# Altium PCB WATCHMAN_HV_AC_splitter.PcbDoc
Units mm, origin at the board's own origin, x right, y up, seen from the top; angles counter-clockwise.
Board outline 37 x 44 mm, 2 copper layers (Top Layer - SIG1, Bottom Layer - SIG4), stack 1.62 mm thick; 16 components, 8 nets, 33 pads, 16 vias.
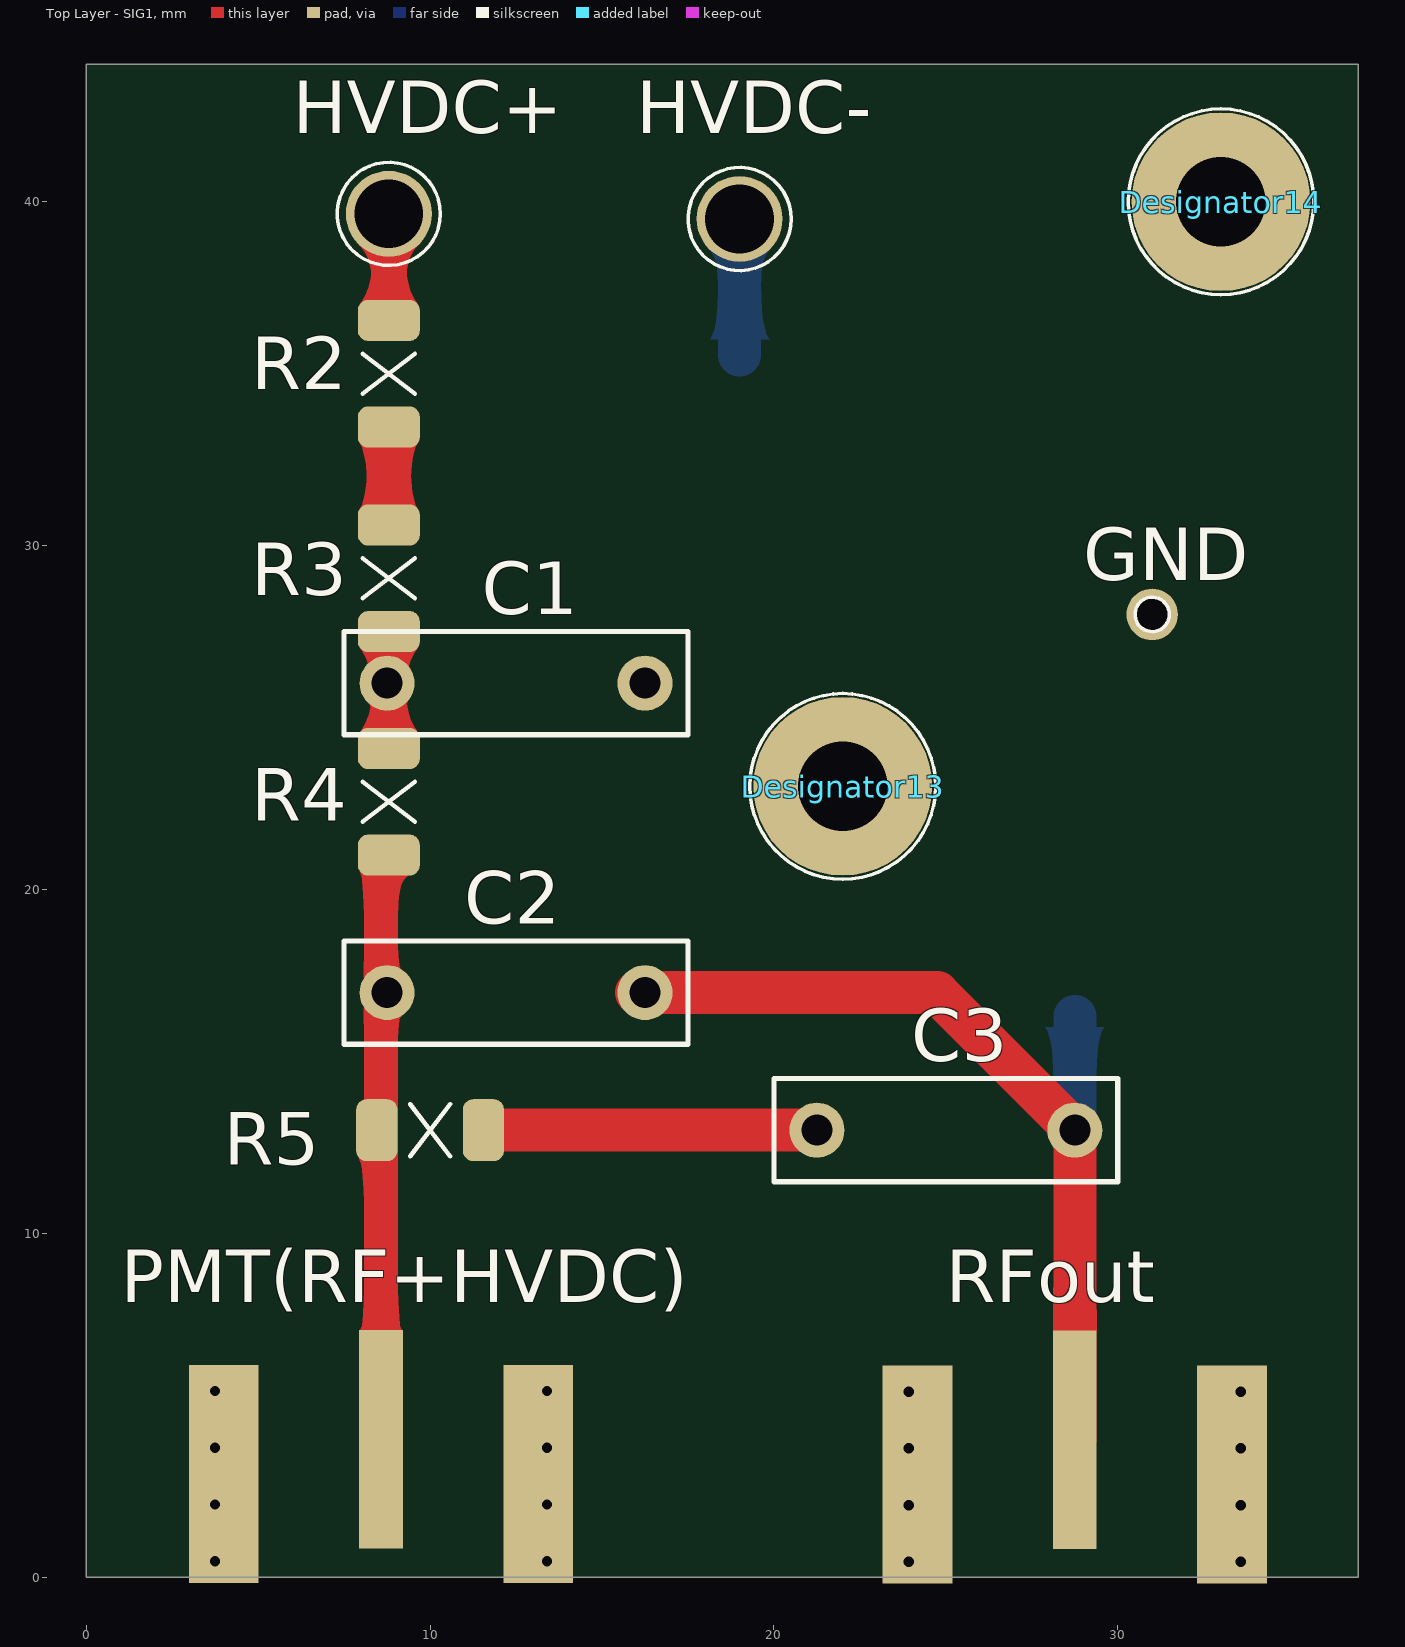
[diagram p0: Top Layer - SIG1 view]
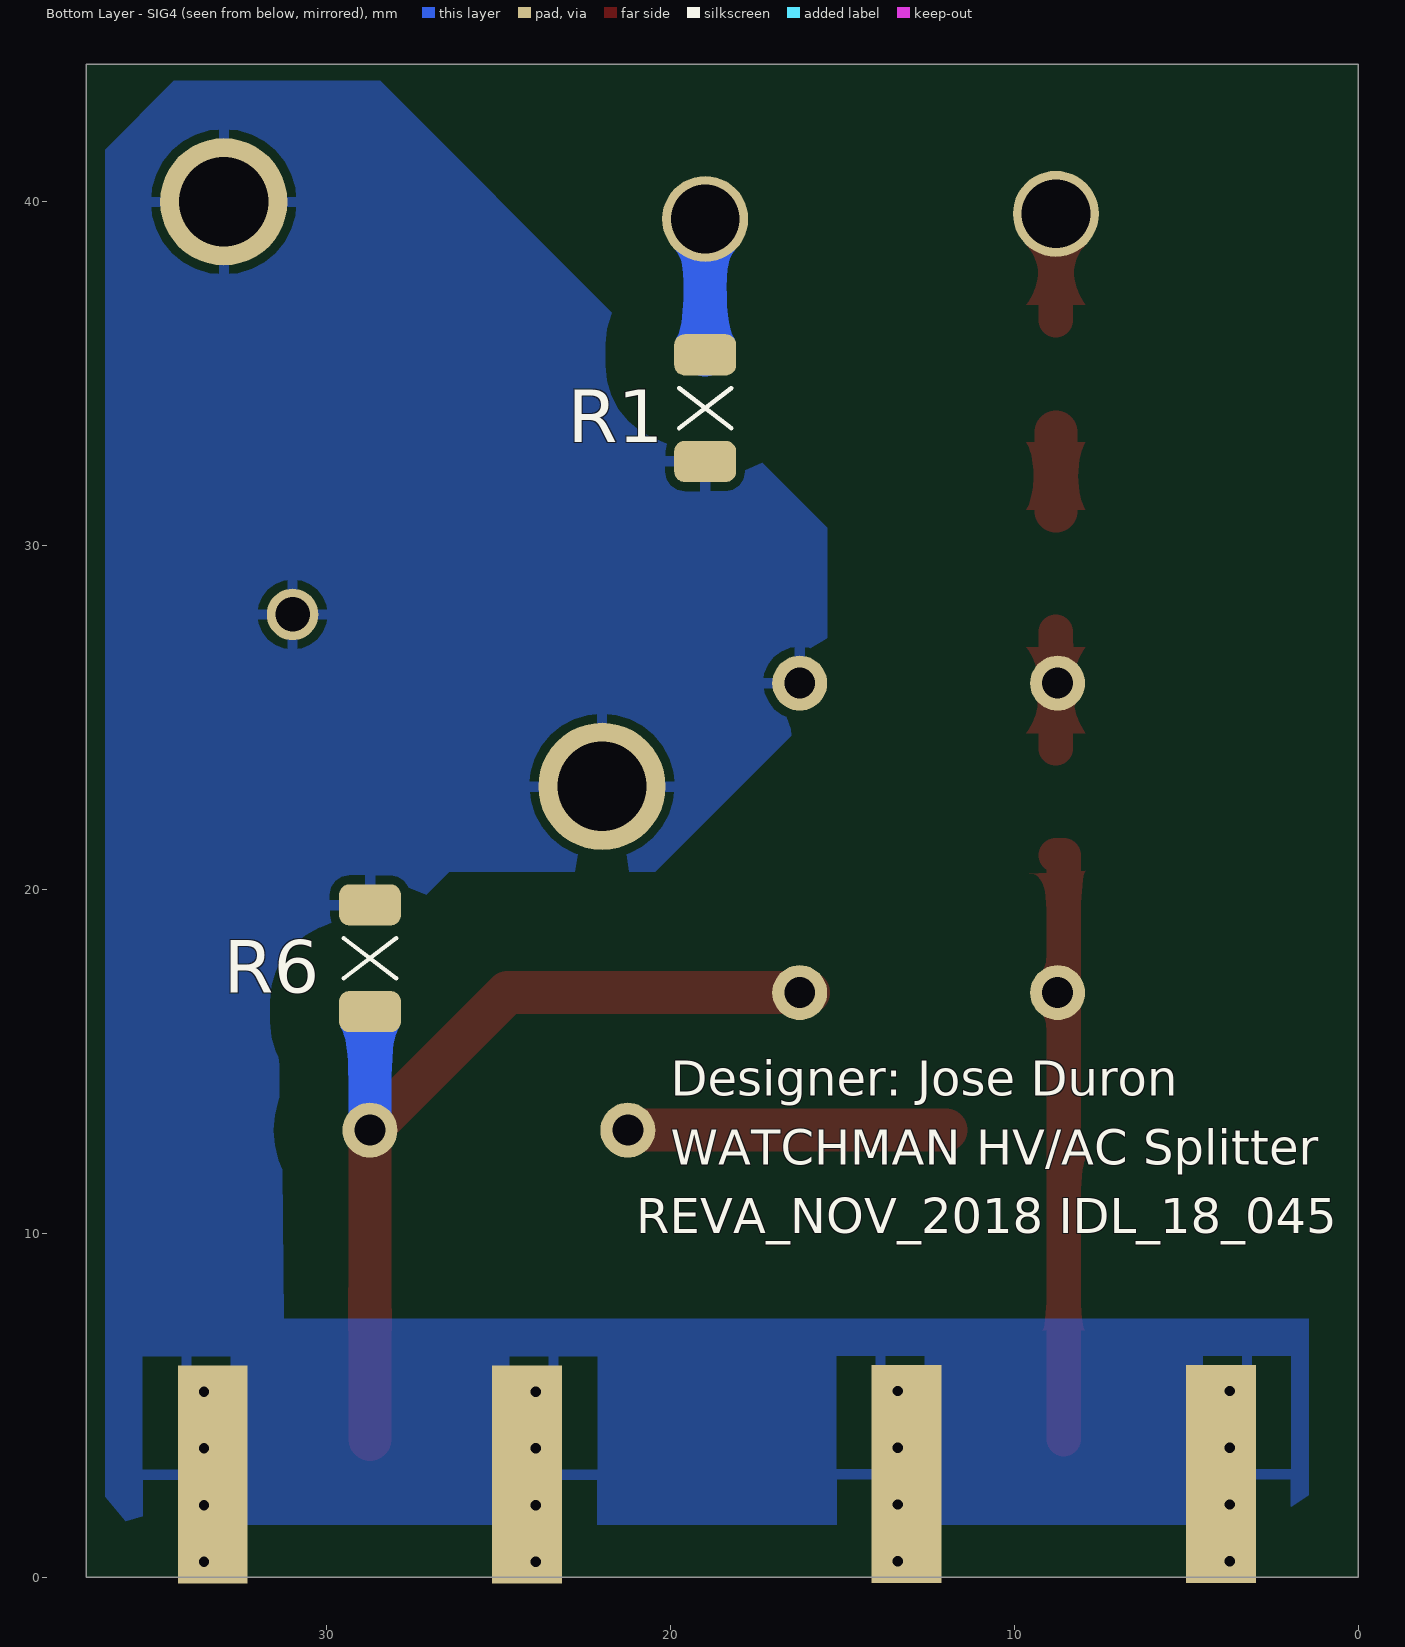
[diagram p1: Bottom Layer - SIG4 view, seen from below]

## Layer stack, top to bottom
Top Solder: solder mask 0.0102, Solder Resist, Dk 3.5
Top Layer - SIG1: signal copper 0.035
Dielectric 1: core 1.55, FR-4, Dk 4.2
Bottom Layer - SIG4: signal copper 0.035
Bottom Solder: solder mask 0.0102, Solder Resist, Dk 3.5

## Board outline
0,0 37,0 37,44 0,44

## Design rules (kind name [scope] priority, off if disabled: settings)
Clearance Clearance_Diff [InAnyDifferentialPair  or InNetClass('INPUT') vs InNamedPolygon('L4_5VAN') or InNamedPolygon('L3_5VAP') or InNamedPolygon('L1_GND') OR InNamedPolygon('L6_GND')   or InNamedPolygon('L3_GND') or InNamedPolygon('L4_GND')] p1: gap=0.381 ignorepadtopadclearanceinfootprint=FALSE except(0: Arc-Hole Track-Hole SMDPad-Hole THPad-Hole Via-Hole Fill-Hole Poly-Hole Region-Hole Text-Hole)
Clearance Clearance_RF [InNetClass('RF') or InNet('HV_BIAS') or InNet('NetCN1_235') vs InNamedPolygon('L4_5VAN') or InNamedPolygon('L3_5VAP') or InNamedPolygon('L1_GND') OR InNamedPolygon('L6_GND')   or InNamedPolygon('L3_GND') or InNamedPolygon('L4_GND')] p2: gap=0.508 ignorepadtopadclearanceinfootprint=FALSE except(0: Arc-Hole Track-Hole SMDPad-Hole THPad-Hole Via-Hole Fill-Hole Poly-Hole Region-Hole Text-Hole)
Clearance Clearance_Poly [InNamedPolygon('L4_5VAN') or InNamedPolygon('L3_5VAP')  or InNamedPolygon('L1_GND')     OR InNamedPolygon('L6_GND')  or InNamedPolygon('L3_GND') or InNamedPolygon('L4_GND')] p3: gap=0.203 ignorepadtopadclearanceinfootprint=FALSE except(0: Arc-Hole Track-Hole SMDPad-Hole THPad-Hole Via-Hole Fill-Hole Poly-Hole Region-Hole Text-Hole; 1: Arc-THPad Track-THPad SMDPad-THPad THPad-THPad)
Clearance Clearance_KeepOut [Iskeepout] p4 off: gap=0.508 ignorepadtopadclearanceinfootprint=FALSE except(0: Arc-Hole Track-Hole SMDPad-Hole THPad-Hole Via-Hole Fill-Hole Poly-Hole Region-Hole Text-Hole)
Clearance [All] p5: gap=2 ignorepadtopadclearanceinfootprint=TRUE except(0: Arc-Text Arc-Hole Track-Text Track-Hole SMDPad-Text SMDPad-Hole THPad-Text THPad-Hole Via-Text Via-Hole Fill-Text Fill-Hole Poly-Text Poly-Hole Region-Text Region-Hole Text-Text Text-Hole; 0.152: Arc-Arc Arc-Track Arc-SMDPad Arc-Via Track-Track Track-SMDPad Track-Via SMDPad-SMDPad SMDPad-Via THPad-Via Via-Via)
ComponentClearance [All] p1 off: gap=0.254 collisioncheckmode=3 verticalgap=0.254 showdistances=FALSE
DiffPairsRouting [All] p1: maxlimit=0.254 minlimit=0.102 mostfreqgap=0.152 toplayer_minwidth=0.102 toplayer_maxwidth=0.305 toplayer_prefwidth=0.203 bottomlayer_minwidth=0.102 bottomlayer_maxwidth=0.305 bottomlayer_prefwidth=0.203 maxuncoupledlength=12.7
Height [All] p1 off: minheight=0 maxheight=25.4 prefheight=12.7
HoleSize [All] p1: absolutevalues=TRUE maxlimit=3.3 minlimit=0.3 maxpercent=80.000 minpercent=20.000
MinimumSolderMaskSliver [All] p1: minsoldermaskwidth=0.127
NetAntennae [All] p1 off: netantennaetolerance=0
PlaneClearance [All] p1: clearance=0.254
PlaneConnect PlaneConnect_vIA [ISvIA] p1: planeconnectstyle=Direct reliefexpansion=0.508 reliefentries=4 reliefconductorwidth=0.254 reliefairgap=0.254
PlaneConnect [All] p2: planeconnectstyle=Direct reliefexpansion=0.305 reliefentries=4 reliefconductorwidth=0.381 reliefairgap=0.203
PolygonConnect PolygonConnect_Via [IsVia or HasFootprint('ChipFET1206-8') or HasFootprint('MAXB2MPCBV') or HasFootprint('MAXB5MPCBV') or HasFootprint('MAXB6MPCBV') or HasFootprint('PINHDR2X20H') or Hasfootprint('PINHDR2X13H')  or HasFootprint('CC1210-X2Y') or HasFootprint('L-COMMCHOKE-4') or HasFootprint('CTC-D7343-43')] p1: connectstyle=Direct reliefconductorwidth=0.254 reliefentries=4 polygonreliefangle="90 Angle" airgapwidth=0.254
PolygonConnect PolygonConnect_Main [All] p2: connectstyle=Relief reliefconductorwidth=0.305 reliefentries=4 polygonreliefangle="90 Angle" airgapwidth=0.254
RoutingVias [All] p1: holewidth=0.3 width=0.65 viastyle="Through Hole" minholewidth=0.3 minwidth=0.65 maxholewidth=1 maxwidth=1.5
SilkToSilkClearance [All] p1: silktosilkclearance=0.127
SilkToSolderMaskClearance SilkscreenOverComponentPads [IsPad] p1: minsilkscreentomaskgap=0.127 clearancetoexposedcopper=TRUE
SolderMaskExpansion [All] p1: expansion=0.051
Width Width_Logo [HasFootprint('ITECH_LOGO')] p1: maxlimit=0.254 minlimit=0.025 preferedwidth=0.051
Width [All] p2: maxlimit=3.81 minlimit=0.1 preferedwidth=1 bottomlayer_minwidth=0 minimp=50.000000 maximp=50.000000 favimp=50.000000
20 further rules are at their usual default settings.

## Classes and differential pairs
component class HV_AC_splitter: C1 C2 C3 GND HVDC+ HVDC- PMT(RF+HVDC) R1 R2 R3 R4 R5 R6 RFout

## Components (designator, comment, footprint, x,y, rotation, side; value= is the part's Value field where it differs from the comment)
C1 "47nF" CAPNQR7.5-3X10X8.5 12.5,26 r0 top
C2 "1nF" CAPNQR7.5-3X10X8.5 12.5,17 r0 top
C3 "4.7nF" CAPNQR7.5-3X10X8.5 25,13 r0 top
Designator13 "Comment" MH2.5SCRPL 22,23 r0 top
Designator14 "Comment" MH2.5SCRPL 33,40 r0 top
GND "TEST-POINT-SURFACE-MOUNT" TPH0.5S#1 31,28 r90 top
HVDC+ "TEST-POINT-SURFACE-MOUNT" TPH0.5S#2 8.8,38.65 r0 top
HVDC- "TEST-POINT-SURFACE-MOUNT" TPH0.5S#3 19,38.5 r90 top
PMT(RF+HVDC) "UCBBJE20-1" UCBBJE20-1 8.572,5.921 r90 top
R1 "200" CC1206N1R 19,34 r90 bottom
R2 "10k" CC1206N1R 8.8,35 r90 top
R3 "10k" CC1206N1R 8.8,29.05 r90 top
R4 "10k" CC1206N1R 8.8,22.55 r90 top
R5 "22" CC1206N1R 10,13 r180 top
R6 "10k" CC1206N1R 28.75,18 r270 bottom
RFout "UCBBJE20-1" UCBBJE20-1 28.75,5.905 r90 top

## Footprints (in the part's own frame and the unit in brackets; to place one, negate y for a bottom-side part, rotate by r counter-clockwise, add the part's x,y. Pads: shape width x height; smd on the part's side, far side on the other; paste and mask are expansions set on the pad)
CAPNQR7.5-3X10X8.5 [mm] "Capacitor plastic 10x3x8.5mm R7.5"
  round 1.6 hole 0.9: 1(-3.75,0) 2(3.75,0)
  silkscreen extent -5,-1.5 5,1.5, body extent -5,-1.5 5,1.5, height 8.5
CC1206N1R [mm] "Chip capacitor 1206 ROUNDED PAD"
  rrect50% 1.2x1.8 smd: 1(-1.55,0) 2(1.55,0)
  silkscreen extent -0.58,-0.76 0.58,0.76, body extent -1.6,-0.8 1.6,0.8, height 1.35
MH2.5SCRPL [mm] "Mounting Hole 2.6mm; Screw 2.5mm DIN7985A plated hole"
  round 5.2 / inner round 3.7 / far side round 3.7 hole 2.6 paste-2: 1(0,0)
  silkscreen extent -2.7,-2.7 2.7,2.7, body extent -2.5,-2.49 2.48,2.5, height 2
TPH0.5S#1 [mm] "Test point TH 0.5mm slim"
  round 1.5 hole 1: 1(0,0)
  silkscreen extent -0.5,-0.5 0.5,0.5
TPH0.5S#2 [mm] "Test point TH 0.5mm slim"
  round 2.5 hole 2: 1(0,1)
  silkscreen extent -1.5,-0.5 1.5,2.5
TPH0.5S#3 [mm] "Test point TH 0.5mm slim"
  round 2.5 hole 2: 1(1,0)
  silkscreen extent -0.5,-1.5 2.5,1.5
UCBBJE20-1 [mil] "Circuit Board Bulkhead Edge Mount  Coax “BNC” Style Receptacle"
  rect 250x50 smd: 1(-75,0)
  rect 250x80 smd: 2(-115,180) 2(-115,-180)
  rect 250x80 smd far side: 2(-115,180) 2(-115,-180)
  body extent -1003,-281 0,280, height 279

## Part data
C1 C2 C3: library part CAPCC1206_100N200VX7R, "Capacitor chip ceramic 1206", Manufacturer="Kemet, Farnell", Manufacturer No="C1206C106K8RAC , 1288264", Package="Cap Chip 1206"
PMT(RF+HVDC) RFout: "75R Circuit Board Bulkhead Edge Mount  Coax “BNC” Style Receptacle", Manufacturer=Trompeter
R1 R2 R3 R4 R5 R6: library part RES1206, "Chip Resistor 1206", Package="Res Chip 1206"

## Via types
v1: diameter 0.6, hole 0.3, Top Layer - SIG1 to Bottom Layer - SIG4, 16 vias

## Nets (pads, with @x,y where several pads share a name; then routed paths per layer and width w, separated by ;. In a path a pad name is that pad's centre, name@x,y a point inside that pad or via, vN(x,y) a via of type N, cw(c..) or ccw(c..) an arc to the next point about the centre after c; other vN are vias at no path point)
GND: C1.2 Designator13.1 Designator14.1 GND.1 PMT(RF+HVDC).2 R1.1 R6.1 RFout.2
  other v1: 23.924,0.444 33.576,0.444 3.746,0.46 13.398,0.46 23.924,2.095 33.576,2.095 3.746,2.111 13.398,2.111 23.924,3.746 33.576,3.746 3.746,3.762 13.398,3.762 23.924,5.397 33.576,5.397 3.746,5.413 13.398,5.413
NetC1_1: C1.1 R3.1 R4.2 | length 3.4
  Top Layer - SIG1 w1: R4.2 R3.1
NetC2_1: C2.1 PMT(RF+HVDC).1 R4.1 R5.2 | length 17.2
  Top Layer - SIG1 w1: 8.572,4.016 8.572,21 R4.1
NetC2_2: C2.2 C3.2 R6.2 RFout.1 | length 26.7
  Top Layer - SIG1 w1.25: C2.2@16,17 24.75,17 C3.2 RFout.1
  Bottom Layer - SIG4 w1.25: C3.2 R6.2@28.75,16.3
NetC3_1: C3.1 R5.1 | length 9.2
  Top Layer - SIG1 w1.25: R5.1@12,13 C3.1
NetHVDC+_1: HVDC+.1 R2.2 | length 3.1
  Top Layer - SIG1 w1: R2.2 HVDC+.1
NetHVDC-_1: HVDC-.1 R1.2 | length 3.9
  Bottom Layer - SIG4 w1.25: R1.2 HVDC-.1
NetR2_1: R2.1 R3.2 | length 2.3
  Top Layer - SIG1 w1.25: R3.2@8.8,31 R2.1@8.8,33.3

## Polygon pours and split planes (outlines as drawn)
GND on Bottom Layer - SIG4 "L3_+7V" (solid, remove dead copper, pour order 2): 34.449,43.518 28.449,43.518 15.449,30.518 15.449,25.518 20.449,20.518 26.449,20.518 31.339,15.627 31.258,7.518 1.449,7.518 1.449,1.518 35.759,1.518 36.449,2.335 36.449,41.518

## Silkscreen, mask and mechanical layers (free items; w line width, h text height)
Bottom Overlay:
  text "Designer: Jose Duron" at 20,14 h1.02
  text "WATCHMAN HV/AC Splitter" at 20,12 h1.02
  text "REVA_NOV_2018 IDL_18_045" at 21,10 h1.02
Board Outline:
  lines w0.102: 0,0 37,0 37,44 12.25,44 0,44 0,12 0,0
Sheet Top:
  lines w0.099: -23.58,-205.777 377.738,-205.777 377.738,85.812 -23.58,85.812 -23.58,-205.777 ; -21.033,-203.245 375.191,-203.245 375.191,83.28 -21.033,83.28 -21.033,-203.245
  lines w0.1: 205.274,-203.245 205.274,-185.206 375.191,-185.206 ; 205.274,-194.331 375.2,-194.331 ; 205.274,-191.302 327.702,-191.302 ; 205.274,-188.254 327.702,-188.254 ; 243.501,-194.331 243.501,-185.206 ; 268.901,-194.331 268.901,-185.206 ; 309.287,-194.331 309.287,-185.206 ; 327.702,-203.245 327.702,-185.206 ; 327.702,-189.778 375.191,-189.778
  text "Designer:" at 205.909,-187.492 h2.54
  text ".Designer" at 220.26,-187.619 h2.54
  text "Revision:" at 244.136,-187.619 h2.54
  text ".Version" at 258.36,-187.619 h2.54
  text "File:" at 269.536,-187.619 h2.54
  text ".Pcb_File_Name_No_Path" at 274.616,-187.619 h2.54
  text "Sheet  1 of  1" at 310.049,-187.619 h2.54
  text "Code:" at 328.337,-188.762 h2.54
  text "Drawn By:" at 205.909,-190.54 h2.54
  text ".Drawn_By" at 220.26,-190.54 h2.54
  text "Modif. Date:" at 244.136,-190.667 h2.54
  text "Date" at 256.963,-190.667 h2.54
  text "Variant:" at 269.536,-190.667 h2.54
  text ".VariantName" at 278.807,-190.667 h2.54
  text "ID:" at 328.464,-193.334 h2.54
  text "Approved By:" at 205.909,-193.588 h2.54
  text ".Approved_By" at 220.26,-193.588 h2.54
  text "Print Date:" at 244.136,-193.715 h2.54
  text ".Print_Date" at 256.963,-193.715 h2.54
  text "Signature:" at 269.536,-193.715 h2.54
  text "Size:  A3 H" at 310.049,-193.715 h2.54
  text "Title:" at 205.909,-196.89 h2.54
  text "University of Hawaii at Manoa" at 328.5,-197.1 h2.54
  text "High Energy Physics Group" at 328.5,-199.6 h2.54
  text ".Printout_Name" at 211.624,-200.446 h4.06
  text "Instrumentation Development Laboratory" at 328.5,-202.2 h2.54
Sheet Bot:
  lines w0.099: -23.587,-205.772 -23.587,85.817 377.731,85.817 377.731,-205.772 -23.587,-205.772 ; -21.04,-203.24 -21.04,83.285 375.184,83.285 375.184,-203.24 -21.04,-203.24
  lines w0.1: -21.049,-194.326 148.877,-194.326 ; -21.04,-189.773 26.449,-189.773 ; -21.04,-185.201 148.877,-185.201 148.877,-203.24 ; 26.449,-203.24 26.449,-185.201 ; 26.449,-191.297 148.877,-191.297 ; 26.449,-188.249 148.877,-188.249 ; 44.864,-194.326 44.864,-185.201 ; 85.25,-194.326 85.25,-185.201 ; 110.65,-194.326 110.65,-185.201
  text "Designer:" at 148.242,-187.487 h2.54
  text "Sheet  1 of  1" at 44.102,-187.614 h2.54
  text ".Pcb_File_Name_No_Path" at 79.535,-187.614 h2.54
  text "File:" at 84.615,-187.614 h2.54
  text ".Version" at 95.791,-187.614 h2.54
  text "Revision:" at 110.015,-187.614 h2.54
  text ".Designer" at 133.891,-187.614 h2.54
  text "Code:" at 25.814,-188.757 h2.54
  text ".Drawn_By" at 133.891,-190.535 h2.54
  text "Drawn By:" at 148.242,-190.535 h2.54
  text ".VariantName" at 75.344,-190.662 h2.54
  text "Variant:" at 84.615,-190.662 h2.54
  text "Date" at 97.188,-190.662 h2.54
  text "Modif. Date:" at 110.015,-190.662 h2.54
  text "ID:" at 25.687,-193.329 h2.54
  text ".Approved_By" at 133.891,-193.583 h2.54
  text "Approved By:" at 148.242,-193.583 h2.54
  text "Size:  A3 H" at 44.102,-193.71 h2.54
  text "Signature:" at 84.615,-193.71 h2.54
  text ".Print_Date" at 97.188,-193.71 h2.54
  text "Print Date:" at 110.015,-193.71 h2.54
  text "Title:" at 148.242,-196.885 h2.54
  text "University of Hawaii at Manoa" at 25.602,-197.2 h2.54
  text "High Energy Physics Group" at 25.602,-199.7 h2.54
  text ".Printout_Name" at 142.527,-200.441 h4.06
  text "Instrumentation Development Laboratory" at 25.602,-202.3 h2.54
FabNTop:
  text ".IDLnum" at 335.957,-188.762 h4.06
  text "ASSEMBLY" at 310.05,-190.7 h2.54
  text ".BoardName" at 335.957,-193.334 h4.06
FabNBot:
  text ".IDLnum" at 18.194,-188.757 h4.06
  text "ASSEMBLY" at 44.1,-190.7 h2.54
  text ".BoardName" at 18.194,-193.329 h4.06
PCBNTop:
  text ".IDLnum" at 335.957,-188.762 h4.06
  text "PCB" at 310.05,-190.7 h2.54
  text ".BoardName" at 335.957,-193.334 h4.06
PCBNBot:
  text ".IDLnum" at 18.2,-188.75 h4.06
  text "PCB" at 44.1,-190.7 h2.54
  text ".BoardName" at 18.194,-193.329 h4.06
Drill Drawing:
  drawing of 229 lines, arcs and shapes, not listed
  text "Notes:" at 226.438,51.086 h3.3
  text "1. Board shall be fabricated - performace class II as per IPC-6011 and IPC6012" at 226.438,47.911 h2.54
  text "2. PCB manufacturer logo, P/N, revision and/or date code of manufacturing" at 226.438,44.736 h2.54
  text "shall be printed in top solder mask (not over pcb traces, allowed over copper plane)." at 228.978,42.196 h2.54
  text "The date code shall be in the format: \"WWYY\" where WW=week and YY= year, max height 0.15 inches" at 228.978,39.656 h2.54
  text "3. Silkscreen not printed on both sides" at 226.438,36.481 h2.54
  text "4. Material: high temperature FR4 class epoxy glass rated UL94V-0. UL symbol and rating shall be marked farside" at 226.438,33.306 h2.54
  text "35um copper for external layers and 18um for all internal layers" at 228.978,30.766 h2.54
  text "Must be RoHS compliant and survive a lead-free assembly max reflow of 260 deg C (5 passes)" at 228.978,28.226 h2.54
  text "Td rating: >340 deg C" at 230.248,25.051 h2.54
  text "Tg = 150 deg C (min)" at 230.35,22.25 h2.54
  text "5. Solder mask: SMOBC per IPC-SM-840C, class T must be Rohs compliant, 0.001\" max measured over bare copper plating," at 226.438,16.161 h2.54
  text "must clear all lands as indicated on gerber solder mask layers, color= GREEN" at 228.978,13.621 h2.54
  text "6. Finish: electro-less nickel immersion gold (ENIG), 0.05-0.125um Au over 3-6um Ni - over bare copper only" at 226.432,9.714 h2.54
  text "7. Solderability test: Category 2 of J-STD-003" at 226.438,6.001 h2.54
  text "8. Finished boards shall not have nicks, scratches, voids, exposed copper, poor plating or misdrilled holes" at 226.438,2.191 h2.54
  text "9. All holes sizes are after plating" at 226.438,-1.619 h2.54
  text "10. PCB manufacturer may add copper thieving as needed to improve manufacturability," at 225.168,-5.429 h2.54
  text "thieving to be 0.030\" round pads at 0.050\" spacing." at 228.978,-7.969 h2.54
  text "Thieving will have a minimum of 0.100\" clearance from existing copper and should not be placed under surface mounted devices" at 228.978,-10.509 h2.54
  text "11. PCB manufacturer may use tear drops to improve annular rings as long as DRC rules are followed" at 225.295,-14.065 h2.54
  text "12. All via connections to power and ground planes are solid" at 225.295,-17.621 h2.54
  text "13. All unconnected pads on inner signal layers are removed" at 225.295,-21.177 h2.54
  text "14. All finished boards are to be 100% electrically tested" at 225.295,-24.733 h2.54
  text "15. Unless otherwise indicated, all linear toleracnes shall be XX.X +/-0.2mm and XX.XX +/- 0.1mm" at 225.295,-28.289 h2.54
  text "16. Gerber file GM1 shows board outline (milling line)" at 225.294,-31.846 h2.54
  text "17. Table 1 shows Layer stack details" at 225.294,-35.402 h2.54
  text "Additional notes:" at 225.422,-42.132 h3.3
  text "A1. Finished board thickness = 1.27mm +/- 0.1mm; measured over top/bottom copper and solder mask" at 225.422,-45.688 h2.54
  text "Table 1a: Layer Stack Details for IDL_14_35 Rev.B (Imperial Units)" at 225,-65 h2.5
  text "Layer" at 224.041,-76.094 h1.52
  text "Name" at 234.453,-76.094 h1.52
  text "Material" at 265.686,-76.094 h1.52
  text "Thickness" at 287.524,-76.094 h1.52
  text "Constant" at 304.03,-76.094 h1.52
  text "Board Layer Stack" at 318.504,-76.094 h1.52
  text "1" at 224.041,-79.142 h1.52
  text "Top Overlay" at 234.453,-79.142 h1.52
  text "2" at 224.041,-82.19 h1.52
  text "Top Solder" at 234.453,-82.19 h1.52
  text "Solder Resist" at 265.686,-82.19 h1.52
  text "0.40mil" at 287.524,-82.19 h1.52
  text "3.5" at 304.03,-82.19 h1.52
  text "3" at 224.041,-85.238 h1.52
  text "Top Layer - SIG1" at 234.453,-85.238 h1.52
  text "Copper" at 265.686,-85.238 h1.52
  text "1.38mil" at 287.524,-85.238 h1.52
  text "4" at 224.041,-88.286 h1.52
  text "Dielectric 1" at 234.453,-88.286 h1.52
  text "FR-4" at 265.686,-88.286 h1.52
  text "61.02mil" at 287.524,-88.286 h1.52
  text "4.2" at 304.03,-88.286 h1.52
  text "5" at 224.041,-91.334 h1.52
  text "Bottom Layer - SIG4" at 234.453,-91.334 h1.52
  text "Copper" at 265.686,-91.334 h1.52
  text "1.38mil" at 287.524,-91.334 h1.52
  text "6" at 224.041,-94.382 h1.52
  text "Bottom Solder" at 234.453,-94.382 h1.52
  text "Solder Resist" at 265.686,-94.382 h1.52
  text "0.40mil" at 287.524,-94.382 h1.52
  text "3.5" at 304.03,-94.382 h1.52
  text "7" at 224.041,-97.43 h1.52
  text "Bottom Overlay" at 234.453,-97.43 h1.52
  text "Symbol" at 228.477,-120.806 h1.83
  text "Hit Count" at 241.326,-120.806 h1.83
  text "Finished Hole Size" at 259.05,-120.806 h1.83
  text "Plated" at 293.229,-120.806 h1.83
  text "Hole Type" at 306.078,-120.806 h1.83
  text "Table 2: NC Drill Details for IDL_14_35 Rev.B" at 226,-124 h2.5
  text "1" at 241.326,-124.616 h1.52
  text "39.37mil (1.000mm)" at 259.05,-124.616 h1.52
  text "PTH" at 293.229,-124.616 h1.52
  text "Round" at 306.078,-124.616 h1.52
  text "2" at 241.326,-128.426 h1.52
  text "78.74mil (2.000mm)" at 259.05,-128.426 h1.52
  text "PTH" at 293.229,-128.426 h1.52
  text "Round" at 306.078,-128.426 h1.52
  text "2" at 241.326,-132.236 h1.52
  text "102.36mil (2.600mm)" at 259.05,-132.236 h1.52
  text "PTH" at 293.229,-132.236 h1.52
  text "Round" at 306.078,-132.236 h1.52
  text "6" at 241.326,-136.046 h1.52
  text "35.43mil (0.900mm)" at 259.05,-136.046 h1.52
  text "PTH" at 293.229,-136.046 h1.52
  text "Round" at 306.078,-136.046 h1.52
  text "16" at 241.326,-139.856 h1.52
  text "11.81mil (0.300mm)" at 259.05,-139.856 h1.52
  text "PTH" at 293.229,-139.856 h1.52
  text "Round" at 306.078,-139.856 h1.52
  text "27 Total" at 241.326,-143.666 h1.52

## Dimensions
37,0 to 37,44 on Drill Drawing
0,44 to 37,44 on Drill Drawing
